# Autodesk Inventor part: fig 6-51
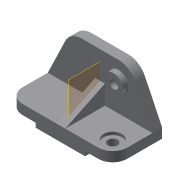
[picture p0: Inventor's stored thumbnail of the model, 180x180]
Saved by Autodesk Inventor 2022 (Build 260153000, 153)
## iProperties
Created: 2001-12
Part Number: fig 6-51
Document SubType Name: Modeling
Designer: Renu Muthoo
Density: 1 g/cm^3
Material: Generic
Appearance: Default
Control State: 0
Master: False
Checked Out: False
Shininess: 77.0
Length Units: 11269
Angle Units: 11279
Time Units: 11290
Mass Units: 11283
Length Display Precision: 3
Angle Display Precision: 2
Density: 0.0
Volumn: 0.0
Area: 0.0
PropertySet Name: Model Information
Author: Renu Muthoo
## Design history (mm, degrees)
node "Sketch1"
sketch "Sketch2"
  geometry: L1 (-67.219, 19.116)-(148.781, 19.116); L2 (148.781, 19.116)-(148.781, -0.884); L3 (-67.219, -0.884)-(-67.219, 19.116); L4 (-10.219, -0.884)-(-10.219, -9.884); L5 (-10.219, -9.884)-(91.781, -9.884); L6 (91.781, -9.884)-(91.781, -0.884); L7 (148.781, -0.884)-(91.781, -0.884); L8 (-10.219, -0.884)-(-67.219, -0.884)
  constraints: 16 end point, 5 parallel, 4 perpendicular, 2 equal length, 1 horizontal
  dimensions: "d0" = 102 distance of L4.end L5.end; "d1" = 57 distance of L4.start L3.start; "d2" = 29 distance between parallel lines of L1 L5; "d3" = 20 distance of L1.end L2.end
extrude "Extrusion1" new body sketch "Sketch2" distance "d4" = 102; taper "d5" = 0 deg
sketch "Sketch3"
  geometry: L1 (67.219, -19.116)-(-148.781, -19.116) reference; L2 (67.219, -19.116)-(31.475, -93.564); L3 (-2.781, -115.116)-(-78.781, -115.116); L4 (-113.038, -93.564)-(-148.781, -19.116); A1 r 38 centre (-2.781, -77.116) between (-2.781, -115.116) and (31.475, -93.564); A2 r 38 centre (-78.781, -77.116) between (-113.038, -93.564) and (-78.781, -115.116)
  constraints: 6 end point, 4 point on circle, 4 tangent, 2 centre point, 1 equal length, 1 equal radius, 1 parallel
  dimensions: "d6" = 96 distance between parallel lines of L3 L1; "d7" = 38 radius of A1; "d8" = 76 distance of A2.centre A1.centre
extrude "Extrusion2" join sketch "Sketch3" distance "d9" = 20; taper "d10" = 0 deg
fillet "Fillet1" dims "d11" = 30
workplane "Work Plane1"
sketch "Sketch5"
  geometry: A1 r 30 centre (-30, 0) between (-30, -30) and (0, 0) reference; 1 further point
  constraints: 1 coincident
hole "Hole1" sketch "Sketch5" at (-30, 0) diameter "d16" = 20; stored, may be unused: countersink angle "d20" = 82 deg, drill point angle "d22" = 118 deg; dims "d17" = 6, "d18" = 38, "d19" = 6, "d21" = 8
sketch "Sketch6"
  geometry: C1 r 19 at (-2.781, 77.116); C2 r 9.5 at (-2.781, 77.116); A1 r 38 centre (-2.781, 77.116) between (31.475, 93.564) and (-2.781, 115.116) reference
  constraints: 2 centre point, 2 coincident
  dimensions: "d23" = 38 diameter of C1; "d24" = 19 diameter of C2
extrude "Extrusion3" join sketch "Sketch6" distance "d25" = 10; taper "d26" = 0 deg
sketch "Sketch7"
  geometry: L1 (0, -82)-(-39.557, 0); L2 (0, -82)-(20, -82) reference; L3 (29, 22.405)-(29, -82); L4 (29, -82)-(0, -82); L5 (0, -82)-(0, 0); L6 (0, 0)-(-90.034, 0); L7 (-90.034, 0)-(-90.034, 22.405); L8 (-90.034, 22.405)-(29, 22.405); L9 (0, 0)-(-74.447, 0) reference
  constraints: 14 end point, 1 collinear, 1 point on line
feature "Rib3" sketch "Sketch7" dims "d35" = 10, "d36" = 20
fillet "Fillet3" dims "d37" = 2
body "Solid1"
other parameters: "d12" = -108
